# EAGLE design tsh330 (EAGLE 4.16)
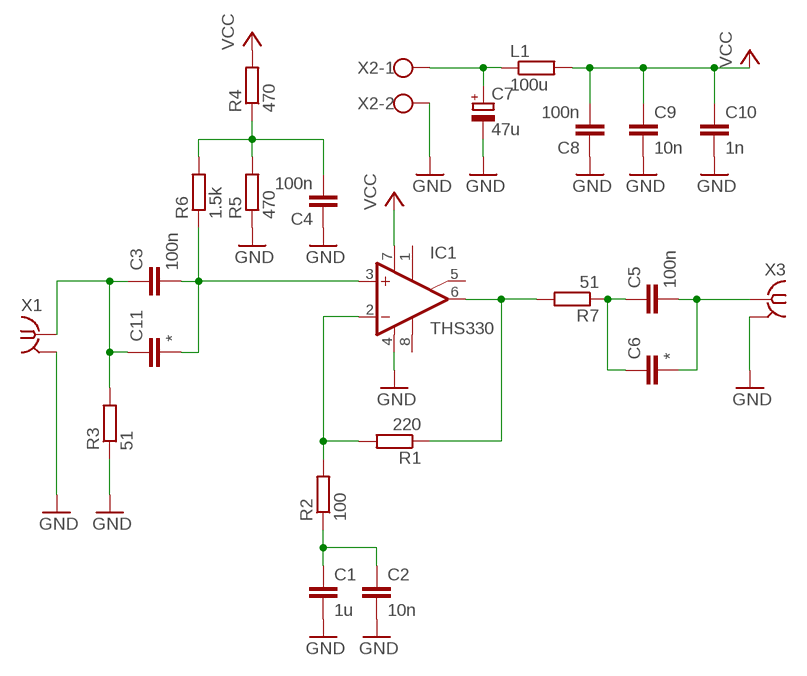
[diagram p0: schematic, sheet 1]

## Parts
C1  1u  C-EUC1210  [C1210]
C2  10n  C-EUC0805  [C0805]
C3  100n  C-EUC1206  [C1206]
C4  100n  C-EUC1206  [C1206]
C5  100n  C-EUC1206  [C1206]
C6  *  C-EUC1206  [C1206]
C7  47u  CPOL-EUE2-5  [E2-5]
C8  100n  C-EUC1206  [C1206]
C9  10n  C-EUC0805  [C0805]
C10  1n  C-EUC0805  [C0805]
C11  *  C-EUC1206  [C1206]
IC1  THS330  TL071D  [SO08]
L1  100u  R-EU_0204/5  [0204/5]
R1  220  R-EU_R0603  [R0603]
R2  100  R-EU_R0603  [R0603]
R3  51  R-EU_R1206  [R1206]
R4  470  R-EU_R0603  [R0603]
R5  470  R-EU_R0603  [R0603]
R6  1.5k  R-EU_R0603  [R0603]
R7  51  R-EU_R1206  [R1206]
X1  BU-SMA-V  [BU-SMA-V]
X2  W237-102  [W237-102]
X3  BU-SMA-V  [BU-SMA-V]

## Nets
GND: C1.2 C2.2 C4.1 C7.- C8.1 C9.2 C10.2 IC1.4(V-) R3.1 R5.1 X1.2(GND) X2.2 X3.2(GND)
N$1: IC1.2(-IN) R1.2 R2.2
N$2: IC1.6(OUT) R1.1 R7.2
N$3: C1.1 C2.1 R2.1
N$5: C4.2 R4.1 R5.2 R6.2
N$6: C3.2 C11.2 IC1.3(+IN) R6.1
N$7: C3.1 C11.1 R3.2 X1.1
N$8: C5.1 C6.1 R7.1
N$9: C5.2 C6.2 X3.1
N$10: C7.+ L1.1 X2.1
VCC: C8.2 C9.1 C10.1 IC1.7(V+) L1.2 R4.2
Unconnected: IC1.1(ON1) IC1.5(ON2) IC1.8(OPT)

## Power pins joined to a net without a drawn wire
GND: X1.3(GND) X1.4(GND) X1.5(GND) X3.3(GND) X3.4(GND) X3.5(GND)

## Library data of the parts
C1-C6 C8-C11 = rcl:C-EU: CAPACITOR, European symbol
C7 = rcl:CPOL-EU: POLARIZED CAPACITOR, European symbol
IC1 = linear:TL071: OP AMP
L1 R1-R7 = rcl:R-EU_: RESISTOR, European symbol
X1 X3 = con-coax:BU-SMA-V: FEMALE SMA CONNECTOR Radiall distributor RS 112-3794
X2 = con-wago-500:W237-102: WAGO SCREW CLAMP

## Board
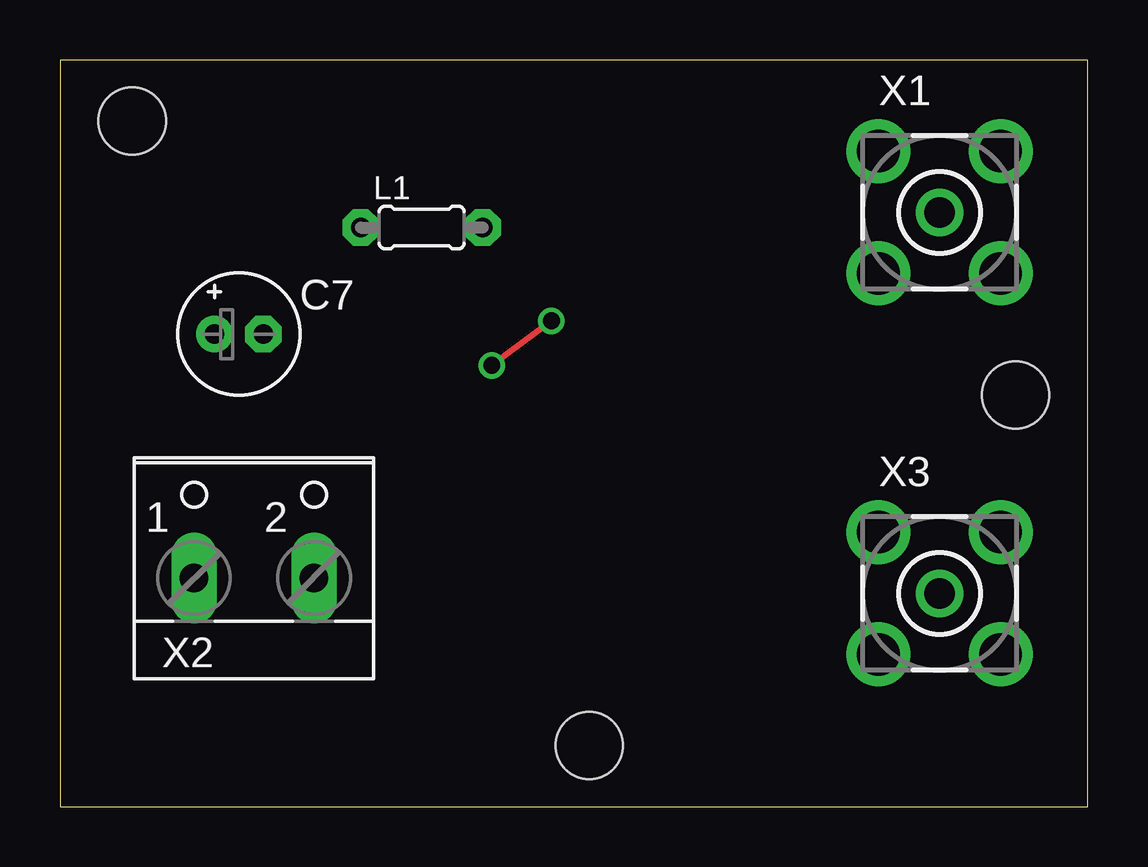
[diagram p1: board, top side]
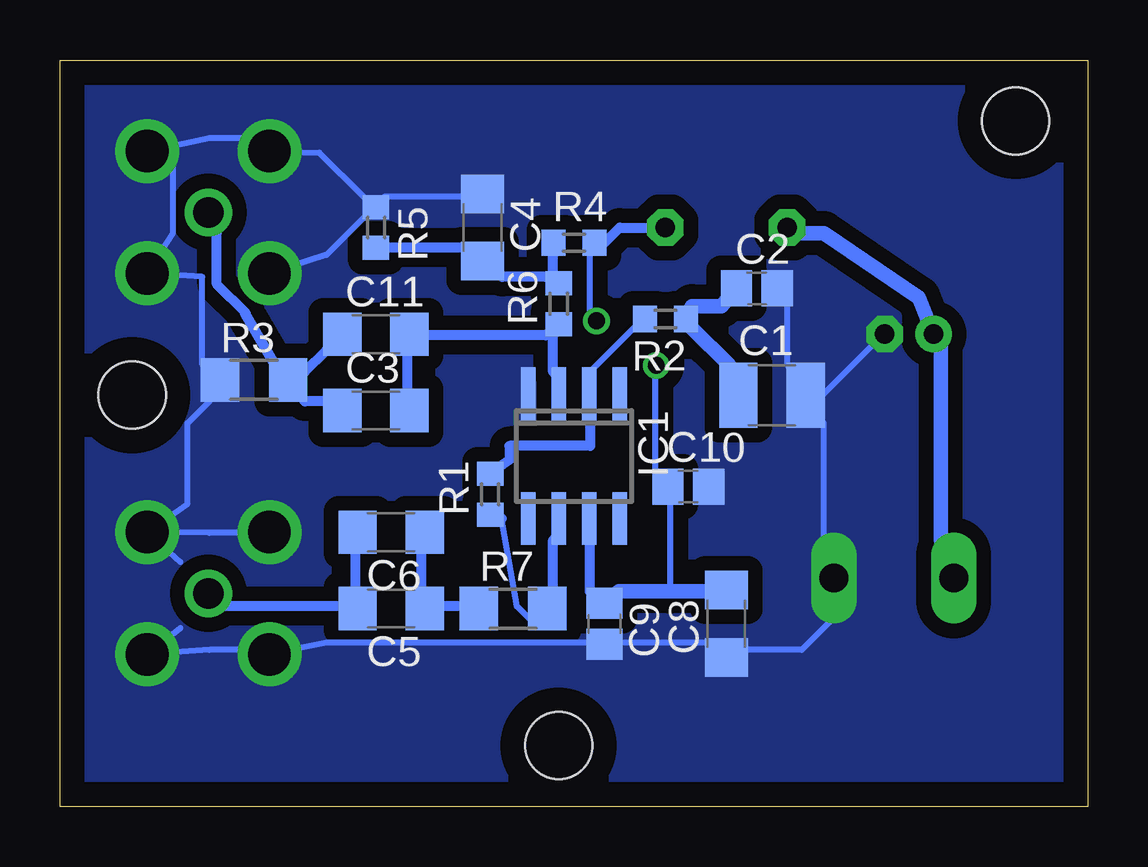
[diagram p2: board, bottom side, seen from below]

Size 42.85 x 31.11 mm. Coordinates in mm from the lower left corner, seen from the top.
Outline: 0,0 42.85,0 42.85,31.11 0,31.11 0,0
Copper layers (1*16): Top 0.035mm / dielectric 1.5mm / Bottom 0.035mm
Design rules "default": minimum track width 10mil, minimum drill 24mil, track to track 8mil, track to pad 8mil, pad to pad 8mil, via to via 8mil, smd to smd 8mil, copper to edge 40mil, drill to drill 8mil, minimum pad ring 14mil, minimum via ring 8mil, stop-mask expansion 4mil, vias tented up to drill 0mil, thermal gap 10mil
Holes 2.8 mm at 3.01,28.57 39.84,17.14 22.06,2.54

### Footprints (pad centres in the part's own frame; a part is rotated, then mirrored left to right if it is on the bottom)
C1210 = smd 1.6 x 2.7: 1 -1.4,0; 2 1.4,0
C0805 = smd 1.3 x 1.5: 1 -0.85,0; 2 0.85,0
C1206 = smd 1.6 x 1.8: 1 -1.4,0; 2 1.4,0
E2-5 = drill 0.813 pad 1.27 round: + -1.016,0 | drill 0.813 pad 1.27 octagon: - 1.016,0
SO08 = smd 0.6 x 2.2: 1 -1.905,-2.6; 2 -0.635,-2.6; 3 0.635,-2.6; 4 1.905,-2.6; 5 1.905,2.6; 6 0.635,2.6; 7 -0.635,2.6; 8 -1.905,2.6
0204/5 = drill 0.813 octagon: 1 -2.54,0; 2 2.54,0
R0603 = smd 1 x 1.1: 1 -0.85,0; 2 0.85,0
R1206 = smd 1.6 x 1.803: 1 -1.422,0; 2 1.422,0
BU-SMA-V = drill 1.27 round: 1 0,0 | drill 1.778 round: 2 -2.55,2.55; 3 2.55,2.55; 4 2.55,-2.55; 5 -2.55,-2.55
W237-102 = drill 1.194 long: 1 -2.5,-1.27; 2 2.5,-1.27

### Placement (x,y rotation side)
C1  13.17,17.14 0 bottom
C2  13.8,21.59 0 bottom
C3  29.68,16.5 0 bottom
C4  25.23,24.12 270 bottom
C5  29.05,8.25 180 bottom
C6  29.05,11.43 180 bottom
C7  7.45,19.68 0 top
C8  15.08,7.61 90 bottom
C9  20.16,7.61 270 bottom
C10  16.66,13.33 0 bottom
C11  29.68,19.68 0 bottom
IC1  21.42,14.6 180 bottom
L1  15.08,24.12 0 top
R1  24.92,13.01 90 bottom
R2  17.62,20.32 180 bottom
R3  34.76,17.78 0 bottom
R4  21.42,23.49 0 bottom
R5  29.68,24.12 270 bottom
R6  22.06,20.95 90 bottom
R7  23.96,8.25 0 bottom
X1  36.66,24.76 0 top
X2  8.09,10.79 0 top
X3  36.66,8.89 0 top

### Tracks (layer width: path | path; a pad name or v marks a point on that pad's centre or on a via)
GND
  Bottom 0.254: C2.2 12.54,20.85 12.54,18.41 C1.2 | C7.- 8.88,19.32 11.01,17.19 C1.2 | C1.2 11.01,15.97 11.01,11.09 X2.2 10.71,7.74 11.93,6.52 14.36,6.52 C8.1 15.89,6.83 19.55,6.83 C9.2 20.77,6.83 31.74,6.83 X3.5 34.18,6.52 36.61,6.52 X3.4 37.83,7.44 | X3.2 34.18,11.4 36.61,11.4 X3.3 | X3.3 37.83,10.18 | R5.1 30.21,24.51 31.74,22.98 X1.5 | C4.1 25.95,25.42 29.3,25.42 R5.1 | R5.1 30.21,25.42 32.04,27.25 X1.2 34.18,27.86 36.61,27.86 X1.3 38.14,26.64 38.14,23.9 X1.4 36.92,22.07 36.92,18.41 R3.1 36.61,16.89 37.53,15.97 37.53,12.62 X3.3
  pour Bottom (isolate 0.61, no thermals): 0.47,31.11 0.47,0.63 42.38,0.63 42.38,31.11
N$1
  Bottom 0.254: R2.2 18.94,19.93 20.77,18.11 IC1.2 20.75,16.58 20.74,16.28
  Bottom 0.406: 20.74,16.28 20.74,15.03 24.12,15.03 24.12,14.45 R1.2
N$2
  Bottom 0.254: 22.29,11.09 IC1.6 | 24.44,12.01 23.8,8.34 23.2,7.74 R7.2
  Bottom 0.406: 22.29,11.09 22.29,8.96 R7.2 | 24.44,12.01 R1.1
N$3
  Bottom 0.61: C1.1 14.97,18.41 16.5,19.93 R2.1 16.5,20.85 15.28,20.85 C2.1
N$5
  Bottom 0.254: 22.59,22.07 R6.2 22.29,22.07 | 24.42,22.07 C4.2
  Bottom 0.406: 22.59,22.07 24.42,22.07 | R5.2 29.3,23.29 25.95,23.29 C4.2 | 22.29,22.07 22.29,22.98 R4.1
N$6
  Bottom 0.254: IC1.3 22.29,18.11 | 27.77,19.63 C11.2
  Bottom 0.406: C3.2 28.38,17.19 28.38,19.02 C11.2 | 22.29,18.11 22.29,19.63 R6.1 22.59,19.63 27.77,19.63
N$7
  Bottom 0.254: 31.74,19.02 C11.1 | R3.2 32.65,18.11 | 35.14,20.54 35.09,20.54
  Bottom 0.406: C3.1 31.74,16.89 32.65,16.89 R3.2 33.87,18.41 35.14,20.54 | 32.65,18.11 31.74,19.02 | 35.09,20.54 36.31,21.76 36.31,23.9 X1.1
N$8
  Bottom 0.254: 27.77,11.4 C6.1 | C5.1 27.77,8.96
  Bottom 0.406: C5.1 26.86,8.35 25.95,8.35 R7.1 | 27.77,8.96 27.77,11.4
N$9
  Bottom 0.254: 30.52,8.96 C5.2 31.13,8.35 | 30.52,11.4 C6.2
  Bottom 0.406: 30.52,8.96 30.52,11.4 | 31.13,8.35 36.01,8.35 X3.1
N$10
  Bottom 0.254: 6.13,19.32 C7.+
  Bottom 0.61: 6.13,19.32 6.13,11.09 X2.1 | L1.1 11.93,23.9 11.01,23.9 7.05,21.2 C7.+
VCC  (via drill 0.7, 0.7 pad 0.61)
  Top 0.254: v18,18.39 v20.48,20.24
  Bottom 0.254: C9.1 20.77,8.96 | C8.2 15.89,8.96 | 17.41,8.96 17.41,12.62 C10.1 18.02,13.84 18.02,18.39 v18,18.39 | v20.48,20.24 20.77,20.24 20.77,22.98 R4.2
  Bottom 0.406: 20.77,8.96 20.77,11.09 IC1.7 | R4.2 20.16,23.49 19.52,24.12 L1.2
  Bottom 0.61: 15.89,8.96 17.41,8.96 19.55,8.96 C9.1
